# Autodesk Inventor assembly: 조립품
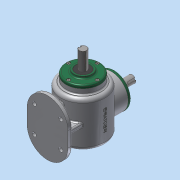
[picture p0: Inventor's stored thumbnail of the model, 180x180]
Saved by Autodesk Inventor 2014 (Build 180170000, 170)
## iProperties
Created: 2023-01
Part Number: 조립품
Document SubType Name: Assembly
Designer: dg
Author: dg
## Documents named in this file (14)
- C:\Users\dg\Desktop\730106V1024\조립품.iam
- C:\Users\dg\Desktop\730106V1024\M4.ipt
- C:\Users\dg\Desktop\730106V1024\메인 베벨기어.ipt
- C:\Users\dg\Desktop\730106V1024\메인 축.ipt
- 메인 축.ipt
- C:\Users\dg\Desktop\730106V1024\베어링 6203.ipt
- C:\Users\dg\Desktop\730106V1024\서브 베벨기어.ipt
- C:\Users\dg\Desktop\730106V1024\서브 축.ipt
- 서브 축.ipt
- C:\Users\dg\Desktop\730106V1024\오일실 17 32 8.ipt
- C:\Users\dg\Desktop\730106V1024\커버.ipt
- C:\Users\dg\Desktop\730106V1024\키 4x4.ipt
- C:\Users\dg\Desktop\730106V1024\키 5x5.ipt
- C:\Users\dg\Desktop\730106V1024\본체.ipt
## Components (8 placed, 1 different names)
1. M4:1
2. M4:3
3. M4:4
4. M4:5
5. M4:2
6. M4:6
7. M4:7
8. M4:8
